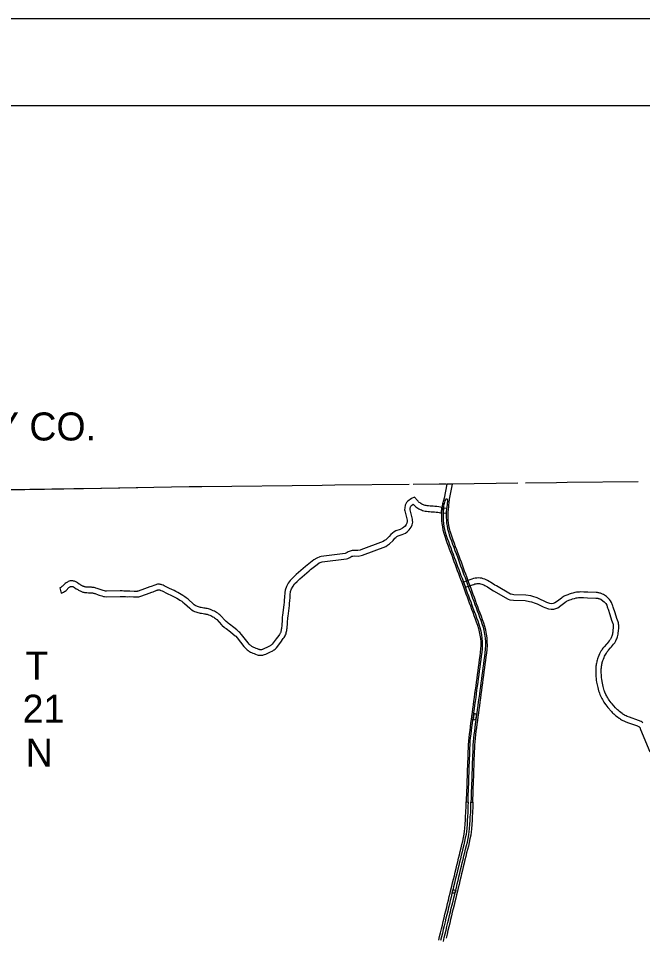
# Model space of a CAD drawing. Extents: x 77230 to 630905, y 790554 to 1662844.
# Drawn here: x 503252 to 531453, y 1621277 to 1662844 of the extents above; entities that cross this region are included whole.
import ezdxf

# ---------------------------------------------------------------- set-up
doc = ezdxf.new("R2010")
doc.units = 0
for name, color, linetype in [('Level 1', 7, 'Continuous'), ('Level 10', 7, 'Continuous'), ('Level 14', 7, 'Continuous'), ('Level 15', 7, 'Continuous'), ('Level 28', 7, 'Continuous')]:
    doc.layers.add(name, color=color, linetype=linetype)

msp = doc.modelspace()

# ---------------------------------------------------------------- linework, layer by layer
at = {"layer": 'Level 1'}
for points in [[(531256, 1641884), (528047, 1641852), (527562, 1641844), (526166, 1641827)], [(516981, 1641721), (511543, 1641660), (510970, 1641654), (506177, 1641574), (505760, 1641572), (501771, 1641506)], [(520907, 1641762), (517544, 1641729), (516981, 1641721)], [(522578, 1641781), (522264, 1641775), (521094, 1641764)], [(525817, 1641823), (522867, 1641786)]]:
    msp.add_lwpolyline(points, dxfattribs=at)
at = {"layer": 'Level 10'}
for points in [[(521149, 1641190), (521009, 1641139), (520845, 1641009), (520793, 1640955), (520755, 1640893), (520731, 1640832), (520707, 1640718), (520702, 1640625), (520707, 1640574), (520810, 1640152), (520814, 1640125), (520814, 1640088), (520801, 1640017), (520777, 1639960), (520724, 1639889), (520654, 1639821), (520606, 1639785), (520502, 1639736), (520311, 1639669), (520226, 1639625), (520147, 1639569), (520080, 1639504), (520001, 1639410), (519856, 1639269), (519798, 1639227), (519738, 1639193), (518727, 1638810), (518686, 1638798), (518585, 1638781), (518447, 1638786), (518330, 1638779), (518237, 1638758), (518146, 1638716), (518098, 1638685), (518049, 1638660), (518021, 1638652), (516928, 1638510), (516863, 1638495), (516729, 1638442), (516600, 1638355), (516304, 1638114), (516229, 1638060), (515800, 1637691), (515664, 1637563), (515532, 1637427), (515446, 1637301), (515362, 1637147), (515305, 1636990)], [(522368, 1640474), (522387, 1640727), (522321, 1640742), (522240, 1640758), (522156, 1640771), (522073, 1640777), (521995, 1640781), (521921, 1640786), (521849, 1640792), (521782, 1640797), (521724, 1640803), (521674, 1640811), (521629, 1640821), (521589, 1640832), (521549, 1640847), (521510, 1640863), (521473, 1640883), (521435, 1640906), (521398, 1640931), (521365, 1640956), (521335, 1640982), (521306, 1641010), (521278, 1641040), (521149, 1641190)], [(515547, 1636925), (515591, 1637044), (515659, 1637171), (515726, 1637268), (515839, 1637384), (515968, 1637505), (516384, 1637863), (516456, 1637916), (516749, 1638154), (516846, 1638219), (516938, 1638256), (516973, 1638264), (518069, 1638407), (518139, 1638425), (518223, 1638468), (518267, 1638496), (518318, 1638520), (518364, 1638530), (518450, 1638536), (518601, 1638530), (518741, 1638554), (518805, 1638572), (519846, 1638966), (519933, 1639017), (520017, 1639077), (520184, 1639239), (520263, 1639334), (520307, 1639376), (520356, 1639411), (520410, 1639439), (520597, 1639504), (520736, 1639570), (520816, 1639630), (520913, 1639723), (520996, 1639835), (521041, 1639944), (521065, 1640066), (521063, 1640144), (521056, 1640199), (520954, 1640617), (520952, 1640632), (520955, 1640685), (520972, 1640760), (520981, 1640783), (520992, 1640802), (521013, 1640823), (521083, 1640878)], [(521083, 1640878), (521166, 1640797), (521208, 1640761), (521253, 1640727), (521299, 1640696), (521350, 1640665), (521403, 1640637), (521457, 1640614), (521513, 1640594), (521569, 1640578), (521628, 1640565), (521691, 1640555), (521760, 1640548), (521829, 1640543), (521902, 1640537), (521980, 1640531), (522057, 1640527), (522129, 1640522), (522197, 1640512), (522267, 1640498), (522368, 1640474)], [(510920, 1636578), (510838, 1636645), (510772, 1636692), (510688, 1636749), (510608, 1636799), (510535, 1636840), (510460, 1636881), (510369, 1636929), (510283, 1636971), (510084, 1637065), (509844, 1637184), (509786, 1637209), (509739, 1637228), (509699, 1637241), (509661, 1637249), (509625, 1637254), (509581, 1637256), (509532, 1637253), (509494, 1637244), (509455, 1637232), (509413, 1637217), (509248, 1637154), (509191, 1637132), (508954, 1637047), (508664, 1636943), (508649, 1636939), (508629, 1636936), (508611, 1636934), (508592, 1636932), (508546, 1636931), (508509, 1636932), (508476, 1636934), (508284, 1636947), (508173, 1636944), (508103, 1636947), (508021, 1636950), (507936, 1636951), (507853, 1636951), (507232, 1636941), (507181, 1636946), (507148, 1636952), (507087, 1636967), (507038, 1636981), (506985, 1637000), (506943, 1637017), (506807, 1637068), (506758, 1637083), (506715, 1637094), (506669, 1637103), (506628, 1637110), (506587, 1637115), (506554, 1637117), (506511, 1637121), (506470, 1637123), (506426, 1637124), (506356, 1637128), (506300, 1637131), (506275, 1637133), (506259, 1637136), (506234, 1637141), (506219, 1637147), (506195, 1637155), (506177, 1637163), (506154, 1637175), (506123, 1637192), (506098, 1637205), (506074, 1637221), (506047, 1637238), (506001, 1637266), (505920, 1637321), (505883, 1637345), (505841, 1637367), (505812, 1637380), (505780, 1637391), (505748, 1637399), (505718, 1637404), (505680, 1637408), (505637, 1637408), (505595, 1637405), (505550, 1637397), (505502, 1637381), (505463, 1637357), (505435, 1637338), (505403, 1637316), (505370, 1637286), (505248, 1637170), (505221, 1637150), (505195, 1637133), (505163, 1637112), (505122, 1637088), (505158, 1636970), (505190, 1636848)], [(524845, 1637177), (524779, 1637219), (524711, 1637262), (524645, 1637304), (524581, 1637345), (524516, 1637385), (524451, 1637424), (524384, 1637457), (524319, 1637484), (524253, 1637507), (524183, 1637524), (524109, 1637536), (524033, 1637540), (523958, 1637537), (523883, 1637527), (523811, 1637510), (523745, 1637489), (523685, 1637467), (523367, 1637353), (523453, 1637118)], [(505190, 1636848), (505222, 1636861), (505257, 1636877), (505294, 1636900), (505332, 1636924), (505364, 1636946), (505408, 1636977), (505538, 1637102), (505559, 1637120), (505577, 1637133), (505597, 1637146), (505609, 1637153), (505612, 1637154), (505625, 1637157), (505645, 1637158), (505668, 1637158), (505684, 1637156), (505698, 1637154), (505710, 1637151), (505720, 1637148), (505732, 1637142), (505756, 1637129), (505782, 1637113), (505865, 1637056), (505914, 1637027), (505938, 1637011), (505971, 1636990), (506003, 1636972), (506039, 1636953), (506070, 1636937), (506102, 1636923), (506135, 1636911), (506164, 1636901), (506209, 1636891), (506244, 1636884), (506284, 1636881), (506342, 1636878), (506415, 1636874), (506462, 1636873), (506496, 1636871), (506534, 1636868), (506562, 1636866), (506593, 1636862), (506625, 1636857), (506661, 1636850), (506690, 1636842), (506726, 1636831), (506853, 1636783), (506897, 1636766), (506962, 1636743), (507022, 1636726), (507094, 1636707), (507147, 1636698), (507223, 1636691), (507855, 1636701), (507934, 1636701), (508016, 1636700), (508093, 1636697), (508171, 1636694), (508279, 1636697), (508459, 1636685), (508496, 1636682), (508547, 1636681), (508607, 1636683), (508633, 1636685), (508659, 1636687), (508699, 1636694), (508738, 1636704), (509038, 1636812), (509278, 1636898), (509337, 1636920), (509501, 1636983), (509536, 1636995), (509558, 1637002), (509569, 1637005), (509584, 1637006), (509601, 1637005), (509618, 1637002), (509635, 1636999), (509652, 1636993), (509691, 1636978), (509740, 1636957), (509975, 1636840), (510175, 1636746), (510255, 1636706), (510343, 1636660), (510415, 1636621), (510480, 1636584), (510551, 1636540), (510630, 1636487), (510686, 1636446), (510761, 1636385)], [(513070, 1634901), (513132, 1634830), (513442, 1634444), (513496, 1634382), (513530, 1634345), (513558, 1634316), (513593, 1634286), (513628, 1634261), (513662, 1634236), (513700, 1634213), (513742, 1634190), (513787, 1634168), (513838, 1634146), (513906, 1634118), (513958, 1634097), (514041, 1634066), (514083, 1634055), (514119, 1634048), (514159, 1634043), (514203, 1634043), (514242, 1634044), (514290, 1634050), (514332, 1634061), (514367, 1634072), (514435, 1634101), (514615, 1634186), (514742, 1634250), (514777, 1634272), (514810, 1634292), (514851, 1634324), (514882, 1634355), (514907, 1634385), (515105, 1634643), (515218, 1634798), (515252, 1634844), (515302, 1634920), (515326, 1634970), (515342, 1635016), (515356, 1635068), (515368, 1635121), (515376, 1635169), (515383, 1635219), (515390, 1635274), (515395, 1635335), (515406, 1635436), (515413, 1635569), (515420, 1635693), (515424, 1635731), (515436, 1635819), (515494, 1636301), (515506, 1636418), (515511, 1636495), (515523, 1636678), (515535, 1636826), (515541, 1636878), (515547, 1636925)], [(515305, 1636990), (515297, 1636944), (515293, 1636908), (515286, 1636850), (515274, 1636696), (515262, 1636512), (515257, 1636440), (515245, 1636329), (515188, 1635851), (515176, 1635763), (515171, 1635714), (515163, 1635582), (515157, 1635455), (515147, 1635359), (515141, 1635302), (515135, 1635253), (515128, 1635206), (515122, 1635168), (515113, 1635127), (515103, 1635089), (515095, 1635066), (515084, 1635044), (515047, 1634988), (515016, 1634945), (514904, 1634793), (514712, 1634542), (514698, 1634524), (514685, 1634512), (514667, 1634498), (514647, 1634485), (514620, 1634469), (514505, 1634410), (514333, 1634329), (514281, 1634307), (514263, 1634301), (514242, 1634296), (514222, 1634293), (514201, 1634293), (514175, 1634293), (514159, 1634295), (514141, 1634299), (514117, 1634305), (514047, 1634331), (514000, 1634349), (513936, 1634377), (513890, 1634396), (513856, 1634412), (513827, 1634428), (513801, 1634444), (513774, 1634464), (513748, 1634483), (513729, 1634499), (513711, 1634517), (513682, 1634549), (513634, 1634604), (513324, 1634991), (513255, 1635069)], [(523453, 1637118), (523716, 1637213), (523769, 1637232), (523825, 1637252), (523878, 1637269), (523929, 1637281), (523980, 1637288), (524031, 1637290), (524082, 1637287), (524133, 1637279), (524183, 1637266), (524232, 1637250), (524280, 1637230), (524330, 1637204), (524387, 1637171), (524448, 1637133), (524512, 1637092), (524578, 1637051), (524644, 1637009), (524715, 1636963)], [(524715, 1636963), (525381, 1636578), (525457, 1636555), (525617, 1636534), (526146, 1636515), (526348, 1636481), (526429, 1636461), (526592, 1636405), (526684, 1636366), (526964, 1636229), (527036, 1636200), (527197, 1636148), (527315, 1636125), (527447, 1636134), (527538, 1636156), (527618, 1636192), (527759, 1636289)], [(527610, 1636490), (527494, 1636411), (527455, 1636393), (527408, 1636382), (527331, 1636377), (527260, 1636391), (527120, 1636436), (527065, 1636458), (526787, 1636594), (526682, 1636638), (526500, 1636701), (526399, 1636726), (526172, 1636765), (525637, 1636783), (525511, 1636800), (525482, 1636809), (524845, 1637177)], [(529688, 1636795), (529645, 1636814), (529610, 1636828), (529586, 1636836), (529553, 1636847), (529517, 1636858), (529481, 1636867), (529443, 1636874), (529413, 1636878), (529349, 1636883), (528974, 1636898), (528793, 1636905), (528659, 1636907), (528598, 1636905), (528534, 1636901), (528466, 1636894), (528390, 1636879), (528307, 1636858), (528218, 1636833), (528141, 1636807), (528075, 1636784), (528024, 1636765), (527982, 1636747), (527940, 1636727), (527906, 1636711), (527862, 1636684), (527819, 1636656), (527789, 1636634), (527610, 1636490)], [(512987, 1635303), (512783, 1635449), (512745, 1635479), (512712, 1635507), (512638, 1635576), (512613, 1635602), (512390, 1635837), (512347, 1635875), (512305, 1635908), (512257, 1635943), (512207, 1635975), (512157, 1636005), (512107, 1636032), (512049, 1636061), (511992, 1636087), (511928, 1636112), (511848, 1636137), (511780, 1636154), (511730, 1636164), (511695, 1636170), (511633, 1636179), (511564, 1636190), (511516, 1636198), (511476, 1636207), (511429, 1636218), (511390, 1636231), (511351, 1636245), (511308, 1636262), (511269, 1636279), (511233, 1636301), (511196, 1636328), (511157, 1636361), (510920, 1636578)], [(527759, 1636289), (527940, 1636435), (527960, 1636450), (527995, 1636473), (528025, 1636490), (528048, 1636502), (528085, 1636519), (528117, 1636533), (528160, 1636549), (528222, 1636571), (528291, 1636594), (528372, 1636616), (528446, 1636635), (528503, 1636647), (528553, 1636652), (528609, 1636655), (528662, 1636657), (528787, 1636655), (528964, 1636648), (529335, 1636633), (529386, 1636630), (529402, 1636627), (529428, 1636623), (529451, 1636617), (529477, 1636609), (529508, 1636599), (529523, 1636594), (529563, 1636577)], [(529563, 1636577), (529662, 1636507), (529722, 1636454), (529786, 1636384)], [(530006, 1636504), (529956, 1636568), (529897, 1636633), (529818, 1636703), (529688, 1636795)], [(530293, 1635714), (530215, 1635959), (530130, 1636215), (530109, 1636277), (530096, 1636315), (530084, 1636350), (530067, 1636392), (530050, 1636425), (530006, 1636504)], [(510761, 1636385), (510991, 1636174), (511041, 1636132), (511095, 1636092), (511153, 1636058), (511210, 1636031), (511262, 1636011), (511311, 1635993), (511363, 1635977), (511420, 1635963), (511467, 1635953), (511523, 1635943), (511595, 1635932), (511658, 1635922), (511686, 1635918), (511724, 1635910), (511781, 1635896), (511845, 1635876), (511896, 1635856), (511941, 1635836), (511990, 1635811), (512034, 1635787), (512076, 1635762), (512114, 1635738), (512153, 1635709), (512186, 1635683), (512216, 1635656), (512434, 1635428), (512465, 1635397), (512545, 1635321), (512586, 1635286), (512633, 1635249), (512842, 1635100)], [(529786, 1636384), (529830, 1636306), (529840, 1636288), (529849, 1636264), (529859, 1636235), (529872, 1636195), (529893, 1636135), (529978, 1635882), (530055, 1635638)], [(530265, 1634737), (530289, 1634789), (530302, 1634838), (530314, 1634878), (530331, 1634941), (530344, 1635002), (530352, 1635060), (530361, 1635132), (530375, 1635286), (530378, 1635343), (530376, 1635403), (530369, 1635458), (530357, 1635510), (530345, 1635549), (530293, 1635714)], [(513255, 1635069), (513214, 1635109), (513127, 1635194), (512987, 1635303)], [(530055, 1635638), (530106, 1635475), (530116, 1635444), (530123, 1635414), (530127, 1635384), (530128, 1635346), (530126, 1635303), (530112, 1635159), (530104, 1635093), (530097, 1635044), (530088, 1634999), (530073, 1634947), (530061, 1634906), (530053, 1634875), (530033, 1634832)], [(512842, 1635100), (512962, 1635005), (513041, 1634929), (513070, 1634901)], [(530033, 1634832), (530014, 1634800), (529998, 1634774), (529984, 1634752), (529969, 1634730), (529945, 1634700), (529847, 1634580), (529818, 1634545), (529713, 1634425), (529686, 1634393), (529661, 1634360), (529633, 1634320), (529604, 1634276), (529573, 1634225), (529541, 1634169), (529509, 1634105), (529480, 1634039), (529448, 1633966), (529431, 1633923), (529415, 1633878), (529401, 1633829), (529389, 1633783)], [(529632, 1633723), (529642, 1633763), (529653, 1633801), (529665, 1633836), (529679, 1633870), (529709, 1633938), (529736, 1633998), (529762, 1634051), (529789, 1634099), (529815, 1634142), (529840, 1634180), (529862, 1634212), (529880, 1634235), (529903, 1634262), (530008, 1634383), (530040, 1634421), (530140, 1634543), (530170, 1634580), (530193, 1634614), (530212, 1634644), (530228, 1634672), (530247, 1634702), (530265, 1634737)], [(529389, 1633783), (529379, 1633741), (529369, 1633694), (529359, 1633640), (529352, 1633595), (529346, 1633547), (529341, 1633498), (529338, 1633438), (529338, 1633381), (529338, 1633268), (529343, 1633133), (529345, 1633080), (529352, 1632996), (529361, 1632925), (529377, 1632823)], [(529624, 1632861), (529609, 1632960), (529600, 1633022), (529594, 1633096), (529592, 1633143), (529588, 1633272), (529588, 1633381), (529588, 1633433), (529590, 1633481), (529594, 1633516), (529600, 1633559), (529606, 1633600), (529614, 1633645), (529623, 1633685), (529632, 1633723)], [(529377, 1632823), (529425, 1632584), (529460, 1632443)], [(529700, 1632511), (529669, 1632639), (529624, 1632861)], [(529460, 1632443), (529483, 1632371), (529499, 1632326), (529519, 1632278), (529567, 1632173), (529610, 1632083), (529636, 1632037), (529664, 1631988), (529681, 1631959), (529703, 1631924), (529735, 1631877), (529784, 1631807), (529834, 1631741), (529881, 1631684), (530044, 1631500), (530084, 1631459), (530114, 1631430), (530150, 1631395), (530196, 1631357), (530250, 1631311), (530317, 1631256), (530387, 1631203), (530421, 1631179), (530460, 1631152), (530506, 1631125), (530557, 1631098), (530602, 1631078), (530661, 1631050), (530768, 1631008), (531182, 1630864), (531217, 1630852), (531242, 1630842), (531262, 1630831), (531279, 1630820), (531298, 1630804), (531314, 1630788), (531324, 1630776), (531336, 1630756), (531350, 1630727), (531365, 1630692)], [(531467, 1630989), (531429, 1631020), (531390, 1631046), (531348, 1631068), (531306, 1631086), (531264, 1631100), (530855, 1631242), (530760, 1631280), (530707, 1631305), (530668, 1631323), (530628, 1631343), (530594, 1631364), (530563, 1631385), (530536, 1631404), (530472, 1631452), (530410, 1631503), (530357, 1631548), (530318, 1631580), (530288, 1631610), (530260, 1631636), (530228, 1631670), (530071, 1631846), (530031, 1631895), (529986, 1631955), (529941, 1632019), (529913, 1632061), (529895, 1632088), (529880, 1632114), (529853, 1632161), (529833, 1632197), (529794, 1632278), (529748, 1632380), (529731, 1632417), (529720, 1632451), (529700, 1632511)], [(531365, 1630692), (531784, 1629685)]]:
    msp.add_lwpolyline(points, dxfattribs=at)
at = {"layer": 'Level 14'}
msp.add_lwpolyline([(508643, 1641611), (506195, 1641574), (500899, 1641477), (495649, 1641406)], dxfattribs=at)
msp.add_lwpolyline([(508643, 1641611), (506195, 1641574), (500899, 1641477), (495649, 1641406)], dxfattribs=at)
at = {"layer": 'Level 15'}
msp.add_line((523011, 1623430), (522975, 1623283), dxfattribs=at)
for points in [[(522862, 1641786), (522607, 1641782), (522482, 1641144)], [(522727, 1641096), (522862, 1641786)], [(522482, 1641144), (522457, 1641038), (522409, 1640891), (522493, 1640878)], [(522493, 1640878), (522505, 1640913), (522533, 1641027), (522558, 1641080), (522577, 1641111), (522606, 1641126)], [(522606, 1641126), (522627, 1641103), (522637, 1641067), (522642, 1641008), (522628, 1640902), (522622, 1640858)], [(522622, 1640858), (522706, 1640846), (522712, 1640940), (522727, 1641096)], [(522493, 1640878), (522409, 1640891), (522394, 1640791), (522380, 1640665), (522370, 1640535), (522365, 1640403), (522366, 1640270), (522373, 1640135), (522387, 1639998), (522407, 1639858), (522434, 1639715), (522469, 1639570), (522513, 1639425), (522563, 1639282), (522615, 1639140), (522668, 1638996), (522721, 1638851), (522775, 1638706), (522829, 1638564), (522881, 1638424), (522931, 1638285), (522982, 1638149), (523031, 1638016), (523080, 1637882), (523130, 1637747), (523180, 1637612), (523230, 1637479), (523279, 1637347), (523327, 1637217), (523374, 1637088), (523421, 1636959), (523469, 1636826), (523520, 1636691), (523571, 1636554), (523622, 1636414), (523673, 1636273), (523725, 1636130), (523778, 1635986), (523832, 1635842), (523886, 1635697), (523940, 1635551), (523992, 1635406), (524039, 1635259), (524076, 1635111), (524105, 1634959), (524125, 1634804), (524137, 1634646), (524139, 1634488), (524132, 1634331), (524116, 1634174), (524094, 1634013), (524071, 1633848), (524049, 1633681), (524027, 1633512), (524003, 1633343), (523980, 1633173), (523957, 1633002), (523934, 1632830), (523911, 1632658), (523887, 1632485), (523864, 1632312), (523841, 1632140), (523818, 1631968), (523795, 1631796), (523772, 1631627), (523749, 1631460), (523727, 1631296), (523705, 1631133), (523682, 1630970), (523661, 1630808), (523640, 1630645), (523619, 1630484), (523599, 1630322), (523584, 1630160), (523573, 1629998), (523566, 1629837), (523562, 1629680), (523556, 1629526), (523551, 1629369), (523545, 1629209), (523539, 1629048), (523533, 1628886), (523527, 1628725), (523522, 1628562), (523516, 1628400), (523511, 1628237), (523505, 1628075), (523499, 1627912), (523493, 1627747), (523487, 1627580), (523482, 1627412), (523567, 1627409)], [(523567, 1627409), (523572, 1627577), (523578, 1627744), (523584, 1627909), (523590, 1628072), (523596, 1628234), (523601, 1628397), (523607, 1628560), (523612, 1628722), (523618, 1628883), (523624, 1629045), (523630, 1629206), (523635, 1629366), (523641, 1629523), (523647, 1629678), (523651, 1629834), (523658, 1629993), (523669, 1630153), (523684, 1630313), (523703, 1630473), (523724, 1630634), (523745, 1630797), (523766, 1630959), (523789, 1631121), (523811, 1631284), (523834, 1631449), (523857, 1631615), (523880, 1631785), (523902, 1631957), (523926, 1632129), (523949, 1632301), (523971, 1632473), (523995, 1632646), (524018, 1632819), (524041, 1632990), (524064, 1633161), (524087, 1633332), (524111, 1633501), (524133, 1633670), (524156, 1633836), (524178, 1634001), (524200, 1634164), (524216, 1634325), (524224, 1634487), (524222, 1634649), (524209, 1634812), (524189, 1634972), (524159, 1635129), (524120, 1635283), (524073, 1635433), (524020, 1635580), (523966, 1635727), (523912, 1635872), (523858, 1636016), (523805, 1636159), (523753, 1636302), (523702, 1636443), (523651, 1636583), (523599, 1636721), (523549, 1636856), (523501, 1636988), (523453, 1637117), (523407, 1637247), (523358, 1637377), (523309, 1637509), (523260, 1637642), (523210, 1637777), (523160, 1637911), (523111, 1638045), (523062, 1638179), (523011, 1638314), (522961, 1638453), (522908, 1638594), (522854, 1638736), (522801, 1638881), (522747, 1639025), (522695, 1639169), (522643, 1639311), (522594, 1639452), (522551, 1639593), (522517, 1639733), (522490, 1639872), (522471, 1640008), (522458, 1640141), (522451, 1640272), (522451, 1640402), (522455, 1640530), (522464, 1640657), (522479, 1640780), (522493, 1640878)], [(522453, 1640465), (522471, 1640715), (522600, 1640700), (522582, 1640450)], [(522622, 1640858), (522607, 1640763), (522594, 1640644), (522585, 1640523), (522581, 1640400), (522581, 1640276), (522588, 1640151), (522600, 1640023), (522619, 1639893), (522644, 1639761), (522677, 1639627), (522718, 1639492), (522766, 1639355), (522817, 1639213), (522869, 1639070), (522923, 1638926), (522976, 1638782), (523030, 1638640), (523083, 1638498), (523133, 1638359), (523184, 1638224), (523233, 1638089), (523282, 1637956), (523331, 1637822), (523381, 1637688), (523431, 1637554), (523480, 1637422), (523529, 1637291), (523576, 1637162), (523623, 1637032), (523671, 1636901), (523721, 1636766), (523773, 1636628), (523824, 1636488), (523875, 1636346), (523927, 1636204), (523980, 1636061), (524034, 1635917), (524088, 1635772), (524142, 1635625), (524196, 1635474), (524245, 1635318), (524286, 1635157), (524317, 1634993), (524339, 1634825), (524352, 1634655), (524354, 1634484), (524346, 1634315), (524329, 1634149), (524307, 1633984), (524284, 1633819), (524262, 1633652), (524240, 1633483), (524216, 1633314), (524193, 1633144), (524170, 1632973), (524147, 1632802), (524124, 1632629), (524100, 1632456), (524077, 1632284), (524054, 1632111), (524031, 1631940), (524008, 1631768), (523985, 1631598), (523962, 1631431), (523940, 1631267), (523918, 1631103), (523895, 1630941), (523874, 1630780), (523853, 1630618), (523832, 1630457), (523813, 1630299), (523798, 1630143), (523788, 1629986), (523781, 1629829), (523777, 1629673), (523771, 1629518), (523765, 1629361), (523760, 1629202), (523754, 1629040), (523748, 1628878), (523742, 1628717), (523737, 1628555), (523731, 1628393), (523726, 1628230), (523720, 1628067), (523714, 1627904), (523708, 1627739), (523702, 1627573), (523697, 1627405), (523782, 1627402)], [(523782, 1627402), (523787, 1627570), (523793, 1627736), (523799, 1627901), (523805, 1628064), (523811, 1628227), (523816, 1628390), (523822, 1628552), (523827, 1628714), (523833, 1628875), (523839, 1629037), (523845, 1629199), (523850, 1629358), (523856, 1629515), (523862, 1629671), (523866, 1629826), (523873, 1629982), (523883, 1630136), (523898, 1630290), (523916, 1630447), (523937, 1630607), (523958, 1630769), (523979, 1630930), (524002, 1631092), (524024, 1631255), (524047, 1631420), (524070, 1631586), (524093, 1631756), (524115, 1631929), (524139, 1632100), (524162, 1632273), (524184, 1632445), (524208, 1632617), (524232, 1632790), (524254, 1632962), (524277, 1633133), (524300, 1633302), (524324, 1633472), (524346, 1633641), (524369, 1633808), (524391, 1633972), (524414, 1634139), (524431, 1634309), (524439, 1634483), (524437, 1634659), (524423, 1634834), (524401, 1635006), (524369, 1635176), (524327, 1635342), (524277, 1635501), (524222, 1635654), (524168, 1635802), (524113, 1635947), (524060, 1636091), (524007, 1636233), (523955, 1636375), (523904, 1636517), (523852, 1636657), (523801, 1636796), (523751, 1636930), (523703, 1637062), (523655, 1637191), (523608, 1637321), (523560, 1637451), (523511, 1637584), (523461, 1637717), (523411, 1637852), (523361, 1637985), (523313, 1638119), (523264, 1638253), (523213, 1638389), (523162, 1638527), (523110, 1638669), (523056, 1638812), (523002, 1638955), (522949, 1639099), (522897, 1639242), (522846, 1639383), (522798, 1639519), (522759, 1639650), (522727, 1639779), (522703, 1639907), (522685, 1640033), (522673, 1640157), (522666, 1640278), (522666, 1640399), (522670, 1640519), (522678, 1640636), (522692, 1640752), (522706, 1640846), (522622, 1640858)], [(522582, 1640450), (522453, 1640465)], [(523956, 1631381), (523922, 1631385), (523899, 1631387), (523893, 1631388), (523883, 1631389), (523851, 1631390), (523825, 1631387), (523791, 1631131)], [(523791, 1631131), (523864, 1631139), (523864, 1631139), (523872, 1631139), (523894, 1631136), (523922, 1631133), (523956, 1631381)], [(522244, 1621159), (522284, 1621329), (522325, 1621499), (522365, 1621668), (522406, 1621836), (522445, 1622004), (522485, 1622170), (522525, 1622333), (522564, 1622493), (522602, 1622653), (522640, 1622813), (522679, 1622971), (522717, 1623130), (522755, 1623286), (522793, 1623443), (522831, 1623599), (522870, 1623757), (522908, 1623917), (522947, 1624077), (522985, 1624237), (523024, 1624396), (523062, 1624553), (523099, 1624708), (523136, 1624864), (523174, 1625019), (523211, 1625175), (523249, 1625333), (523289, 1625491), (523326, 1625644), (523358, 1625800), (523391, 1625955), (523407, 1626098), (523421, 1626211), (523436, 1626428), (523446, 1626592), (523454, 1626760), (523471, 1626934), (523476, 1627229), (523482, 1627412)], [(523482, 1627412), (523567, 1627409), (523561, 1627227), (523556, 1626929), (523539, 1626754), (523531, 1626587), (523521, 1626423), (523505, 1626203), (523491, 1626088), (523475, 1625942), (523441, 1625782), (523409, 1625626), (523371, 1625470), (523332, 1625313), (523294, 1625155), (523257, 1624999), (523219, 1624844), (523181, 1624689), (523144, 1624533), (523106, 1624376), (523068, 1624217), (523029, 1624057), (522991, 1623897), (522952, 1623737), (522914, 1623579), (522876, 1623422), (522838, 1623266), (522799, 1623110), (522761, 1622952), (522723, 1622793), (522685, 1622633), (522646, 1622473), (522607, 1622313), (522568, 1622150), (522528, 1621984), (522488, 1621817), (522448, 1621648), (522407, 1621479), (522367, 1621309), (522326, 1621140)], [(522453, 1621109), (522493, 1621279), (522534, 1621448), (522574, 1621618), (522615, 1621787), (522655, 1621954), (522694, 1622119), (522734, 1622282), (522773, 1622443), (522811, 1622603), (522849, 1622762), (522888, 1622921), (522926, 1623079), (522964, 1623236), (523002, 1623392), (523040, 1623548), (523079, 1623706), (523117, 1623867), (523156, 1624027), (523194, 1624187), (523233, 1624345), (523271, 1624502), (523308, 1624658), (523345, 1624813), (523383, 1624968), (523421, 1625125), (523458, 1625282), (523497, 1625439), (523536, 1625597), (523568, 1625756), (523604, 1625921), (523620, 1626073), (523635, 1626190), (523651, 1626414), (523661, 1626580), (523669, 1626745), (523686, 1626922), (523691, 1627224), (523697, 1627405), (523782, 1627402)], [(523782, 1627402), (523776, 1627222), (523771, 1626917), (523753, 1626739), (523746, 1626576), (523736, 1626408), (523719, 1626182), (523705, 1626063), (523688, 1625907), (523651, 1625738), (523619, 1625579), (523580, 1625419), (523541, 1625262), (523503, 1625105), (523466, 1624948), (523428, 1624793), (523390, 1624638), (523353, 1624483), (523315, 1624325), (523277, 1624167), (523239, 1624007), (523200, 1623847), (523161, 1623686), (523123, 1623528), (523084, 1623371), (523047, 1623216), (523008, 1623059), (522970, 1622901), (522932, 1622742), (522894, 1622583), (522855, 1622423), (522816, 1622262), (522777, 1622099), (522737, 1621934), (522697, 1621767), (522657, 1621598), (522616, 1621429), (522576, 1621259)], [(522844, 1623293), (522880, 1623441), (522934, 1623437), (523011, 1623430)], [(522975, 1623283), (522922, 1623287), (522881, 1623290), (522863, 1623292), (522844, 1623293)]]:
    msp.add_lwpolyline(points, dxfattribs=at)
at = {"layer": 'Level 28'}
for p, q in [((295896, 1662844), (591576, 1662844)), ((586296, 1658884), (311736, 1658884)), ((503891, 1631630), (503891, 1631630))]:
    msp.add_line(p, q, dxfattribs=at)

# ---------------------------------------------------------------- texts
for s, height, p in [('TANEY CO.', 1267.2, (497626, 1643757)), ('T', 1267, (503569, 1632943)), ('21', 1267.2, (503443, 1630996)), ('N', 1267, (503584, 1629008))]:
    msp.add_text(s, height=height, dxfattribs=at).set_placement(p)

doc.saveas('drawing.dxf')
